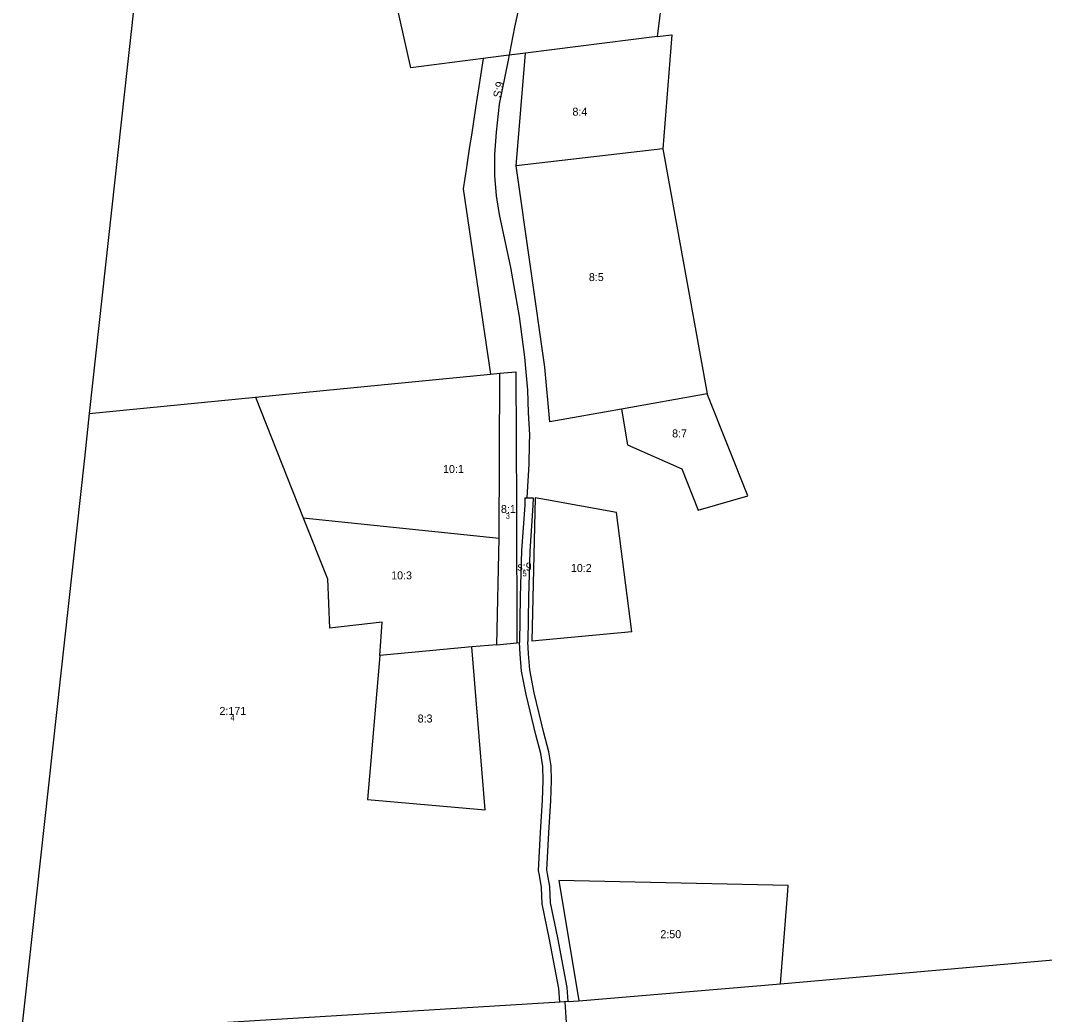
# Model space of a CAD drawing. Extents: x 140824 to 143748, y 6547319 to 6550906.
# Drawn here: x 142376.7 to 142824.6, y 6548750.9 to 6549185.9 of the extents above; entities that cross this region are included whole.
import ezdxf

# ---------------------------------------------------------------- set-up
doc = ezdxf.new("R2010")
doc.units = 0
for name, color, linetype in [('FAST Fastighetsgräns', 7, 'Continuous'), ('FAST Kvarterstraktgräns', 7, 'Continuous'), ('FAST Mittlinjeredovisad samfällighet', 7, 'Continuous'), ('FAST Områdesnummer för fastighet', 7, 'Continuous'), ('FAST Områdesnummer för samfällighet', 7, 'Continuous'), ('FAST Registernummer för fastighet', 7, 'Continuous'), ('FAST Registernummer för mittlinjeredovisad samfällighet', 7, 'Continuous'), ('FAST Registernummer för samfällighet', 7, 'Continuous'), ('FAST Traktgräns', 7, 'Continuous'), ('FAST Tätningsgräns för fastighetsgräns', 7, 'Continuous')]:
    doc.layers.add(name, color=color, linetype=linetype)

msp = doc.modelspace()

# ---------------------------------------------------------------- linework, layer by layer
at = {"layer": 'FAST Fastighetsgräns'}
for p, q in [((142655.13, 6549178.85), (142597.65, 6549171.58)), ((142593.53, 6549122.35), (142597.65, 6549171.58)), ((142657.72, 6549129.69), (142593.53, 6549122.35)), ((142657.72, 6549129.69), (142677.03, 6549022.5)), ((142582.33, 6549031.14), (142586.36, 6549031.53)), ((142406.77, 6549013.95), (142479.47, 6549021.12)), ((142677.03, 6549022.5), (142639.6, 6549015.87)), ((142601.85, 6548977.1), (142600.29, 6548914.26)), ((142500.4, 6548968.27), (142586.07, 6548959.35)), ((142644.15, 6548918.35), (142600.29, 6548914.26)), ((142585.07, 6548912.71), (142593.77, 6548913.55)), ((142574.06, 6548911.82), (142533.94, 6548908.08)), ((142620.93, 6548756.89), (142709.16, 6548764.38)), ((142612.62, 6548756.38), (142436.27, 6548745.52)), ((142616.22, 6548756.6), (142612.62, 6548756.38))]:
    msp.add_line(p, q, dxfattribs=at)
for points in [[(142435.77, 6549277.57), (142423.51, 6549166.73), (142406.77, 6549013.95)], [(142608.76, 6549264.58), (142666.93, 6549273.04), (142655.13, 6549178.85)], [(142655.13, 6549178.85), (142661.62, 6549179.67), (142657.72, 6549129.69)], [(142597.65, 6549171.58), (142586.95, 6549170.31), (142579.08, 6549169.29)], [(142639.6, 6549015.87), (142608.27, 6549010.27), (142606, 6549034.26), (142593.53, 6549122.35)], [(142639.6, 6549015.87), (142642.22, 6549000.26), (142666.02, 6548989.79), (142673.06, 6548971.68), (142694.88, 6548977.95), (142677.03, 6549022.5)], [(142406.77, 6549013.95), (142404.62, 6548994.39), (142376.67, 6548740.04)], [(142644.15, 6548918.35), (142637.42, 6548970.67), (142606.76, 6548976.2), (142601.85, 6548977.1)], [(142612.62, 6548756.38), (142612.19, 6548762.36), (142608.15, 6548783.74), (142604.9, 6548799.4), (142604.59, 6548806.58), (142603.69, 6548811.9), (142603.33, 6548814.04), (142604.14, 6548830.64), (142605.1, 6548844.75), (142605.33, 6548853.33), (142605.19, 6548859.41), (142604.27, 6548865.14), (142602.11, 6548873.35), (142597.91, 6548890.94), (142595.87, 6548901.23), (142595.26, 6548908.57), (142595.02, 6548913.68)]]:
    msp.add_lwpolyline(points, dxfattribs=at)
at = {"layer": 'FAST Kvarterstraktgräns'}
msp.add_line((142616.22, 6548756.6), (142620.93, 6548756.89), dxfattribs=at)
for points in [[(142709.16, 6548764.38), (143032.41, 6548792.85), (143453.49, 6548829.93)], [(142709.16, 6548764.38), (142712.3, 6548805.13), (142712.48, 6548807.47), (142612.14, 6548809.54), (142620.93, 6548756.89)]]:
    msp.add_lwpolyline(points, dxfattribs=at)
at = {"layer": 'FAST Mittlinjeredovisad samfällighet'}
for points in [[(142598.39, 6548977.01), (142599.15, 6548991.83), (142599.37, 6549000.67), (142599.47, 6549004.67), (142598.9, 6549014.4), (142598.66, 6549024.1), (142597.35, 6549038.61), (142594.98, 6549056.41), (142591.18, 6549077.83), (142586.16, 6549100.99), (142584.85, 6549109.15), (142584.22, 6549118.14), (142584.18, 6549127.26), (142584.9, 6549137.04), (142586.28, 6549149.26), (142589.95, 6549167.76), (142592.97, 6549182.99), (142598.97, 6549210.46)], [(142585.58, 6548652.76), (142592.83, 6548654.89), (142598.47, 6548657.22), (142601.64, 6548660.21), (142605.74, 6548665.08), (142610.04, 6548671.99), (142613.92, 6548684.49), (142615.5, 6548698.53), (142616.91, 6548721.66), (142615.99, 6548740.75), (142614.88, 6548756.3), (142614.86, 6548756.52)]]:
    msp.add_lwpolyline(points, dxfattribs=at)
at = {"layer": 'FAST Traktgräns'}
for p, q in [((142586.07, 6548959.35), (142586.36, 6549031.53)), ((142479.47, 6549021.12), (142500.4, 6548968.27)), ((142585.07, 6548912.71), (142586.07, 6548959.35)), ((142585.07, 6548912.71), (142574.06, 6548911.82)), ((142593.77, 6548913.55), (142595.02, 6548913.68))]:
    msp.add_line(p, q, dxfattribs=at)
for points in [[(142579.08, 6549169.29), (142547.42, 6549165.22), (142531.74, 6549235.51)], [(142579.08, 6549169.29), (142577.92, 6549161.77), (142575.75, 6549147.72), (142573.9, 6549135.67), (142573.13, 6549130.72), (142571.9, 6549122.7), (142571.72, 6549121.54), (142570.28, 6549112.21), (142582.33, 6549031.14)], [(142479.47, 6549021.12), (142509.1, 6549024), (142582.33, 6549031.14)], [(142586.36, 6549031.53), (142593.33, 6549032.16), (142593.72, 6548972.84), (142593.77, 6548913.55)], [(142597.35, 6548976.98), (142597.27, 6548973.9), (142595.89, 6548953.93), (142595.29, 6548933.68), (142595.02, 6548913.68)], [(142600.95, 6548977.08), (142600.87, 6548973.74), (142599.49, 6548953.75), (142598.89, 6548933.6), (142598.61, 6548914.11)], [(142500.4, 6548968.27), (142510.92, 6548941.63), (142511.87, 6548920.08)], [(142533.94, 6548908.08), (142534.9, 6548922.7), (142511.87, 6548920.08)], [(142616.22, 6548756.6), (142615.78, 6548762.83), (142611.69, 6548784.44), (142608.49, 6548799.84), (142608.19, 6548806.96), (142607.25, 6548812.5), (142606.95, 6548814.25), (142607.74, 6548830.43), (142608.71, 6548844.58), (142608.95, 6548853.32), (142608.8, 6548859.74), (142607.8, 6548865.89), (142605.61, 6548874.23), (142601.44, 6548891.71), (142599.45, 6548901.73), (142598.87, 6548908.81), (142598.61, 6548914.11)], [(142533.94, 6548908.08), (142528.53, 6548844.98), (142579.99, 6548840.58), (142574.06, 6548911.82)]]:
    msp.add_lwpolyline(points, dxfattribs=at)
at = {"layer": 'FAST Tätningsgräns för fastighetsgräns'}
for p, q in [((142597.35, 6548976.98), (142598.39, 6548977.01)), ((142598.39, 6548977.01), (142600.95, 6548977.08))]:
    msp.add_line(p, q, dxfattribs=at)

# ---------------------------------------------------------------- texts
at = {"layer": 'FAST Områdesnummer för fastighet'}
for s, p in [('3', (142588.9, 6548967.9)), ('4', (142468.5, 6548879.55))]:
    msp.add_text(s, height=2.5, dxfattribs=at).set_placement(p)
at = {"layer": 'FAST Områdesnummer för samfällighet'}
msp.add_text('5', height=2.5, dxfattribs=at).set_placement((142596.29, 6548942.7))
at = {"layer": 'FAST Registernummer för fastighet'}
for s, p in [('8:4', (142618.13, 6549144.26)), ('8:5', (142625.32, 6549071.89)), ('8:7', (142661.74, 6549003.47)), ('10:1', (142561.52, 6548987.91)), ('8:1', (142586.84, 6548970.4)), ('10:2', (142617.44, 6548944.58)), ('10:3', (142538.82, 6548941.36)), ('2:171', (142463.72, 6548882.05)), ('8:3', (142550.41, 6548878.73)), ('2:50', (142656.59, 6548784.36))]:
    msp.add_text(s, height=3.5, dxfattribs=at).set_placement(p)
at = {"layer": 'FAST Registernummer för mittlinjeredovisad samfällighet'}
msp.add_text('S:9', height=3.5, rotation=78.495, dxfattribs=at).set_placement((142586.78, 6549151.88))
at = {"layer": 'FAST Registernummer för samfällighet'}
msp.add_text('s:9', height=3.5, dxfattribs=at).set_placement((142594.04, 6548945.2))

doc.saveas('drawing.dxf')
